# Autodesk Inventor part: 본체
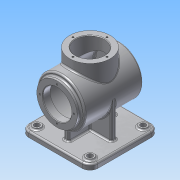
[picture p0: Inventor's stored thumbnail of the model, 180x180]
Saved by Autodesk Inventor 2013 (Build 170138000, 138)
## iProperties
Created: 2015-07
Part Number: 본체
Material: 알루미늄 6061
Document SubType Name: Modeling
Designer: ST
Density: 2.71 g/cm^3
Mass: 1277.74 g
Surface Area: 1267.64 cm^2
Volume: 471.491 cm^3
Author: ST
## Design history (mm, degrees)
sketch "스케치1"
  geometry: L1 (0, 0)-(117, 0); L2 (0, 27)-(0, 38); L3 (0, 38)-(7, 38); L4 (7, 38)-(7, 45); L5 (7, 45)-(117, 45); L6 (117, 45)-(117, 0); L7 (117, 0)-(110, 0); L8 (110, 0)-(110, 40); L9 (110, 40)-(14, 40); L10 (14, 40)-(14, 27); L11 (14, 27)-(0, 27); 1 further point
  constraints: 22 end point, 5 parallel, 4 perpendicular, 2 point on line, 1 coincident, 1 horizontal
  dimensions: "d6" = 7 distance between parallel lines of L2 L4; "d9" = 90 diameter of L5 L1; "d10" = 76 diameter of L3 L1; "d11" = 54 diameter of L11 L1; "d12" = 80 diameter of L9 L1; "d13" = 7 distance between parallel lines of L6 L8; "d14" = 96 distance between parallel lines of L8 L10; "d15" = 14 distance between parallel lines of L2 L10; "d16" = 117 distance of L1.start L1.end; "d17" = 0 distance from line of L1.end L6
revolve "회전1" sketch "스케치1" stored, may be unused: angle "d18" = 90 deg
node "작업 평면2"
sketch "스케치2"
  geometry: L1 (127, 65)-(-3, 65); L2 (-3, 65)-(-3, -65); L3 (-3, -65)-(127, -65); L4 (127, -65)-(127, 65); L5 (117, -45)-(117, 45) reference; 1 further point
  constraints: 8 end point, 2 parallel, 1 horizontal, 1 perpendicular
  dimensions: "d21" = 130 distance of L1.start L1.end; "d24" = 130 distance of L3.end L1.start; "d25" = 65 distance from line of point (0, 0) L1; "d27" = 10 distance between parallel lines of L5 L4
extrude "돌출1" join sketch "스케치2" distance "d28" = 10; taper "d29" = 0 deg
node "작업 평면3"
sketch "스케치3"
  geometry: L1 (-117, 45)-(-117, -45) reference; C1 r 38 at (-62, 0); 1 further point
  constraints: 1 centre point
  dimensions: "d31" = 0 vertical distance of point (0, 0) C1.centre; "d32" = 76 diameter of C1; "d33" = 55 distance from line of L1 C1.centre
extrude "돌출2" join sketch "스케치3" stored distance "d34" = 10; taper "d35" = 0 deg
sketch "스케치4"
  geometry: C1 r 38 at (0, 0) reference; C2 r 27 at (0, 0); 1 further point
  constraints: 1 centre point, 1 coincident
  dimensions: "d36" = 54 diameter of C2
extrude "돌출3" cut sketch "스케치4" stored distance "d38" = 10; taper "d39" = 0 deg
sketch "스케치5" dims "d40" = 64
  geometry: C1 r 27 at (0, 0) reference; C2 r 38 at (0, 0) reference; 3 further points
  constraints: 1 coincident, 1 horizontal alignment, 2 other
  dimensions: "d42" = 0 vertical distance of C1.centre point (32, 0)
hole "구멍1" sketch "스케치5" at (32, 0) diameter "d43" = 3.242; stored, may be unused: countersink angle "d47" = 90 deg, drill point angle "d49" = 118 deg; dims "d44" = 8, "d45" = 4, "d46" = 2, "d48" = 10
sketch "스케치6"
  geometry: L1 (127, 65)-(-3, 65) reference; L2 (-3, 65)-(-3, -65) reference; L3 (-3, -65)-(127, -65) reference; C1 r 7.5 at (12, 50); C2 r 7.5 at (12, -50); 1 further point
  constraints: 2 centre point
  dimensions: "d53" = 15 diameter of C1; "d55" = 15 diameter of C2; "d56" = 15 distance from line of L1 C1.centre; "d57" = 15 distance from line of L2 C1.centre; "d58" = 15 distance from line of L3 C2.centre; "d59" = 15 distance from line of L2 C2.centre
extrude "돌출4" join sketch "스케치6" distance "d60" = 3; taper "d61" = 0 deg
sketch "스케치7"
  geometry: C1 r 7.5 at (0, 0) reference; C2 r 5 at (0, 0); C3 r 7.5 at (0, -100) reference; C4 r 5 at (0, -100); 1 further point
  constraints: 2 centre point, 2 coincident
  dimensions: "d62" = 10 diameter of C2; "d64" = 10 diameter of C4
extrude "돌출5" cut sketch "스케치7" stored distance "d65" = 3; taper "d66" = 0 deg
fillet "모깎기1" dims "d67" = 3
fillet "모깎기2" dims "d71" = 15
sketch "스케치8"
  geometry: L1 (112, 65)-(12, 65) reference; L2 (-3, 50)-(-3, -50) reference; L3 (127, -50)-(127, 50) reference; L4 (107, 5)-(67, 5); L5 (67, 5)-(67, 45); L6 (67, 45)-(57, 45); L7 (57, 45)-(57, 5); L8 (57, 5)-(17, 5); L9 (17, 5)-(17, -5); L10 (17, -5)-(57, -5); L11 (57, -5)-(57, -45); L12 (57, -45)-(67, -45); L13 (67, -45)-(67, -5); L14 (67, -5)-(107, -5); L15 (107, -5)-(107, 5); 1 further point
  constraints: 24 end point, 9 parallel, 4 collinear, 2 perpendicular
  dimensions: "d73" = 10 distance between parallel lines of L7 L5; "d75" = 10 distance between parallel lines of L11 L13; "d76" = 10 distance between parallel lines of L8 L10; "d77" = 10 distance between parallel lines of L14 L4; "d78" = 90 distance between parallel lines of L9 L15; "d79" = 90 distance between parallel lines of L12 L6; "d80" = 20 distance between parallel lines of L2 L9; "d81" = 20 distance between parallel lines of L1 L6; "d82" = 40 distance between parallel lines of L13 L15; "d84" = 40 distance between parallel lines of L6 L8
extrude "돌출6" join sketch "스케치8" stored distance "d85" = 3; taper "d86" = 0 deg
fillet "모깎기3" dims "d87" = 3
chamfer "모따기1" distance "d88" = 1; stored, may be unused: second distance "d89" = 2, angle "d90" = 45 deg
fillet "모깎기4" dims "d91" = 3
sketch "스케치9" dims "d92" = 64
  geometry: C1 r 38 at (0, 0) reference; C2 r 28 at (0, 0) reference; 2 further points
  constraints: 1 coincident, 1 horizontal alignment, 2 other
  dimensions: "d94" = 0 vertical distance of C1.centre point (32, 0)
hole "구멍2" sketch "스케치9" at (32, 0) diameter "d95" = 3.242; stored, may be unused: countersink angle "d99" = 90 deg, drill point angle "d101" = 118 deg; dims "d96" = 8, "d97" = 4, "d98" = 2, "d100" = 10
fillet "모깎기5" dims "d105" = 3
fillet "모깎기6" dims "d106" = 3
fillet "모깎기7" dims "d107" = 3
fillet "모깎기8" dims "d108" = 3
fillet "모깎기9" dims "d109" = 3
sketch "스케치10"
  geometry: L1 (-8.67, -28.311)-(-8.67, 28.311); L2 (-8.67, 28.311)-(8.67, 28.311); L3 (8.67, 28.311)-(8.67, -28.311); L4 (8.67, -28.311)-(-8.67, -28.311); L5 (0, -28.311)-(0, 28.311); L6 (-8.67, 0)-(8.67, 0); C1 r 42 at (0, 0) reference
  constraints: 4 end point, 4 midpoint, 2 other
  dimensions: "d110" = 0 vertical distance of C1.centre L6.start; "d111" = 0 distance from line of C1.centre L5
extrude "돌출7" join sketch "스케치10" distance "d112" = 0.5; taper "d113" = 0 deg
fillet "모깎기10" dims "d114" = 3
node "솔리드1"
pattern_circular "원형 패턴1" dims angle "d51" = 360 deg
pattern_linear "직사각형 패턴1"
pattern_circular "원형 패턴2" dims angle "d103" = 360 deg
node "투영된 루프1"
other parameters: "d20" = -78
